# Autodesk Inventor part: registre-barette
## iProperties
Author: chr
Created: 2001-06
Part Number: registre-barette
Material: Par défaut
Document SubType Name: Modélisation
Designer: chr
Control State: 0
Master: False
Checked Out: False
PropertySet Name: Design Tracking Control
Shininess: 21.0
PropertySet Name: _Private Model Information
Length Units: 11269
Angle Units: 11286
Time Units: 11279
Mass Units: 11290
Length Display Precision: 3
Angle Display Precision: 2
Compacted: False
Density: 0.0
Volumn: 0.0
Area: 0.0
PropertySet Name: Model Information
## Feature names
1. Extrusion1
2. Extrusion2
